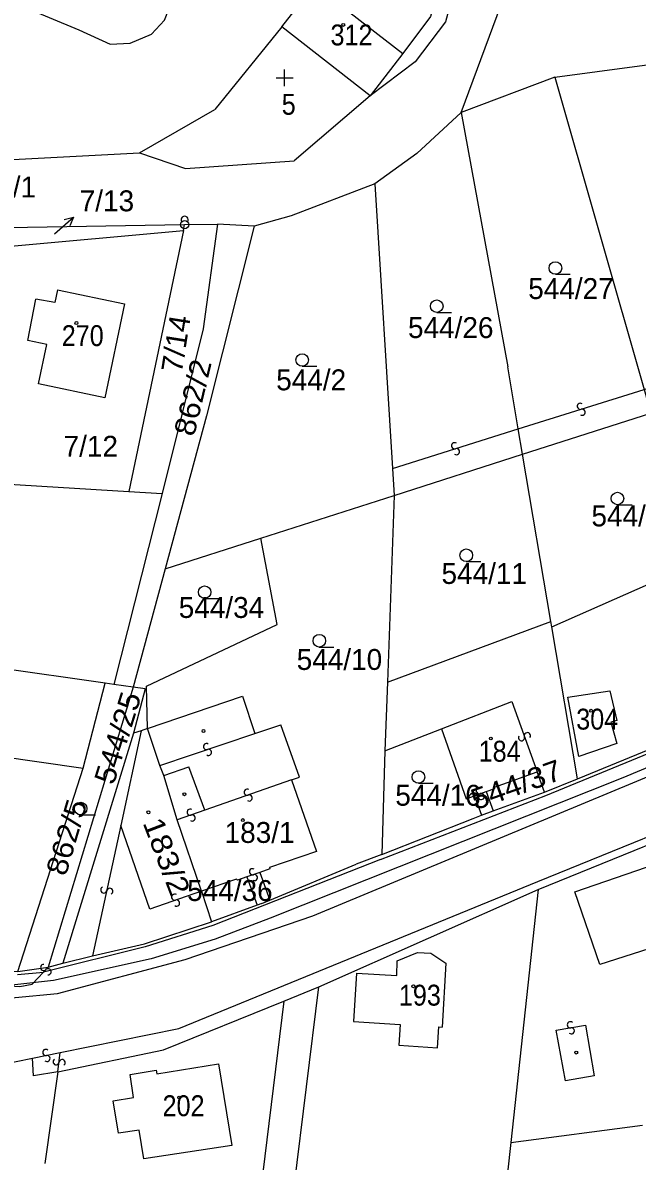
# Model space of a CAD drawing. Extents: x -680102 to -677253, y -1007548 to -1006096.
# Drawn here: x -679602.9 to -679529.5, y -1007099.8 to -1006963.5 of the extents above; entities that cross this region are included whole.
import ezdxf
from ezdxf.enums import TextEntityAlignment as Align

# ---------------------------------------------------------------- set-up
doc = ezdxf.new("R2010")
doc.units = 0
for name, color, linetype, lineweight in [('1', 7, 'Continuous', 25), ('16', 7, 'Continuous', 25), ('24', 7, 'Continuous', 25), ('25', 7, 'Continuous', 25), ('4', 7, 'Continuous', 25)]:
    doc.layers.add(name, color=color, linetype=linetype, lineweight=lineweight)
doc.layers.add('18', color=7, linetype='Continuous')
doc.layers.add('19', color=7, linetype='Continuous')

msp = doc.modelspace()

# ---------------------------------------------------------------- linework, layer by layer
at = {"layer": '1'}
for p, q in [((-679571.97, -1006964), (-679579.98, -1006973.93)), ((-679539.3, -1006970.04), (-679550.54, -1006974.28)), ((-679561.42, -1006972.28), (-679570.49, -1006980.07)), ((-679550.54, -1006974.28), (-679555.81, -1006979.17)), ((-679550.54, -1006974.28), (-679544.95, -1007004.69)), ((-679555.81, -1006979.17), (-679560.85, -1006982.8)), ((-679560.85, -1006982.8), (-679570.85, -1006986.65)), ((-679583.74, -1006988.4), (-679583.59, -1006987.69)), ((-679575.29, -1006987.86), (-679580.97, -1007010.57)), ((-679543.18, -1007015.16), (-679527.83, -1007010.23)), ((-679558.52, -1007020.08), (-679543.18, -1007015.16)), ((-679539.8, -1007035.17), (-679543.18, -1007015.16)), ((-679586.29, -1007019.86), (-679592.07, -1007042.7)), ((-679572.52, -1007035.52), (-679574.48, -1007025.2)), ((-679539.69, -1007035.83), (-679525.44, -1007029.5)), ((-679559.35, -1007042.42), (-679539.8, -1007035.17)), ((-679593.1, -1007042.56), (-679633.83, -1007036.77)), ((-679589.73, -1007043.03), (-679599.91, -1007076.52)), ((-679595.71, -1007052.73), (-679593.1, -1007042.56)), ((-679592.07, -1007042.7), (-679593.1, -1007042.56)), ((-679589.73, -1007043.03), (-679592.07, -1007042.7)), ((-679588.33, -1007043.22), (-679589.73, -1007043.03)), ((-679588.33, -1007043.22), (-679589.71, -1007048.54)), ((-679575.18, -1007048.57), (-679572.07, -1007047.53)), ((-679569.87, -1007053.81), (-679572.07, -1007047.53)), ((-679589.71, -1007048.54), (-679598.16, -1007076.05)), ((-679559.65, -1007050.64), (-679552.89, -1007048.02)), ((-679536.61, -1007054.02), (-679522.23, -1007048.1)), ((-679611.26, -1007050.51), (-679595.71, -1007052.73)), ((-679559.65, -1007050.64), (-679560.02, -1007063.06)), ((-679603.56, -1007077.07), (-679595.71, -1007052.73)), ((-679540.55, -1007055.61), (-679541.44, -1007053.16)), ((-679570.81, -1007054.14), (-679569.87, -1007053.81)), ((-679540.55, -1007055.61), (-679536.61, -1007054.02)), ((-679547.52, -1007055.51), (-679546.68, -1007057.84)), ((-679548.94, -1007056.02), (-679548.09, -1007058.36)), ((-679560.02, -1007063.06), (-679549.1, -1007058.73)), ((-679560.02, -1007063.06), (-679563.08, -1007064.23)), ((-679573.39, -1007064.78), (-679574.59, -1007065.2)), ((-679574.59, -1007065.2), (-679573.42, -1007068.54)), ((-679576.15, -1007065.74), (-679577.28, -1007066.14)), ((-679576.15, -1007065.74), (-679574.91, -1007069.13)), ((-679581.59, -1007067.45), (-679580.36, -1007071.1)), ((-679588.39, -1007073.73), (-679580.36, -1007071.1)), ((-679558.16, -1007075.78), (-679555.74, -1007074.77)), ((-679555.74, -1007074.77), (-679554.15, -1007074.88)), ((-679554.15, -1007074.88), (-679552.34, -1007076.06)), ((-679552.34, -1007076.06), (-679552.81, -1007083.71)), ((-679563.02, -1007077.25), (-679563.39, -1007083.03)), ((-679573.64, -1007128.49), (-679567.53, -1007078.91)), ((-679571.74, -1007080.61), (-679567.53, -1007078.91)), ((-679553.21, -1007083.68), (-679552.81, -1007083.71)), ((-679605.74, -1007088.23), (-679601.79, -1007087.43)), ((-679598.74, -1007089.06), (-679600.32, -1007100.05))]:
    msp.add_line(p, q, dxfattribs=at)
for points in [[(-679550.54, -1006974.28), (-679543.33, -1006954.87), (-679540.17, -1006921.93)], [(-679546.93, -1006924.38), (-679548.35, -1006946.19), (-679548.91, -1006950.64), (-679552.39, -1006963.42), (-679556.03, -1006968.19), (-679561.42, -1006972.28)], [(-679549.48, -1006924.04), (-679550.13, -1006946.36), (-679550.94, -1006951.13), (-679554.18, -1006962.79), (-679557.51, -1006967.2)], [(-679606.93, -1006959.92), (-679596.24, -1006964.38), (-679592.49, -1006966.08), (-679590.1, -1006965.97), (-679587.56, -1006964.91), (-679586.02, -1006963.21), (-679584.89, -1006960.34), (-679584.65, -1006958.11), (-679585.98, -1006955.77), (-679584.33, -1006951.79)], [(-679539.3, -1006970.04), (-679523.55, -1006967.91), (-679513.94, -1007002.8)], [(-679539.3, -1006970.04), (-679528.63, -1007007.41), (-679527.83, -1007010.23)], [(-679610.24, -1006980.22), (-679588.99, -1006979.09), (-679579.98, -1006973.93)], [(-679588.99, -1006979.09), (-679583.5, -1006980.97), (-679570.49, -1006980.07)], [(-679560.85, -1006982.8), (-679558.72, -1007016.85), (-679558.52, -1007020.08)], [(-679609.23, -1006988.1), (-679604.73, -1006988.03), (-679583.59, -1006987.69), (-679579.65, -1006987.63)], [(-679579.65, -1006987.63), (-679581.36, -1007000.14), (-679586.29, -1007019.86)], [(-679570.85, -1006986.65), (-679575.29, -1006987.86), (-679579.65, -1006987.63)], [(-679605.27, -1006990.34), (-679583.74, -1006988.4), (-679590.25, -1007019.62), (-679586.29, -1007019.86)], [(-679605.27, -1006990.34), (-679611.75, -1007018.31), (-679590.25, -1007019.62)], [(-679598.78, -1006995.48), (-679590.77, -1006997.15), (-679593.14, -1007008.42), (-679601.08, -1007006.75), (-679600.09, -1007002.02), (-679602.34, -1007001.54), (-679601.4, -1006996.59)], [(-679598.78, -1006995.48), (-679599.11, -1006997.02), (-679601.4, -1006996.59)], [(-679543.18, -1007015.16), (-679543.69, -1007012.14), (-679544.95, -1007004.69)], [(-679580.97, -1007010.57), (-679585.91, -1007028.87), (-679589.73, -1007043.03)], [(-679585.91, -1007028.87), (-679574.48, -1007025.2), (-679558.52, -1007020.08)], [(-679558.52, -1007020.08), (-679559.35, -1007042.42), (-679559.65, -1007050.64)], [(-679536.61, -1007054.02), (-679539.69, -1007035.83), (-679539.8, -1007035.17)], [(-679588.05, -1007047.98), (-679588.15, -1007042.91), (-679572.52, -1007035.52)], [(-679581.59, -1007067.45), (-679584.47, -1007058.91), (-679586.1, -1007053.62), (-679586.54, -1007052.41), (-679588.05, -1007047.98), (-679576.69, -1007044.12), (-679575.18, -1007048.57)], [(-679514.77, -1007046.84), (-679521.17, -1007049.71), (-679531.18, -1007053.87), (-679573.37, -1007070.68), (-679579.96, -1007073.17), (-679587.61, -1007075.54), (-679599.28, -1007078.15)], [(-679588.05, -1007047.98), (-679588.81, -1007048.24), (-679589.71, -1007048.54)], [(-679552.89, -1007048.02), (-679549.93, -1007056.38), (-679548.94, -1007056.02)], [(-679547.52, -1007055.51), (-679546.49, -1007055.14), (-679546.54, -1007055), (-679541.44, -1007053.16)], [(-679570.81, -1007054.14), (-679567.84, -1007062.68), (-679573.45, -1007064.62), (-679573.39, -1007064.78)], [(-679549.1, -1007058.73), (-679548.09, -1007058.36), (-679546.68, -1007057.84), (-679540.55, -1007055.61)], [(-679567.53, -1007078.91), (-679541.32, -1007067.26), (-679516, -1007056.97)], [(-679574.37, -1007068.93), (-679573.42, -1007068.54), (-679563.08, -1007064.23)], [(-679577.28, -1007066.14), (-679577.37, -1007066), (-679581.59, -1007067.45)], [(-679541.32, -1007067.26), (-679544.6, -1007097.51), (-679528.85, -1007095.43)], [(-679574.37, -1007068.93), (-679574.91, -1007069.13), (-679580.36, -1007071.1)], [(-679599.28, -1007078.15), (-679604.24, -1007078.68), (-679609.24, -1007078.8), (-679614.25, -1007078.59), (-679645.06, -1007075.26), (-679644.83, -1007073.22)], [(-679644.83, -1007073.22), (-679638.88, -1007073.91), (-679622.01, -1007075.9), (-679613.12, -1007076.97), (-679603.56, -1007077.07), (-679599.91, -1007076.52), (-679598.16, -1007076.05)], [(-679598.16, -1007076.05), (-679594.6, -1007075.19), (-679588.39, -1007073.73)], [(-679563.02, -1007077.25), (-679558.23, -1007077.55), (-679558.16, -1007075.78)], [(-679598.74, -1007089.06), (-679586.13, -1007086.43), (-679571.74, -1007080.61), (-679580.62, -1007153.16)], [(-679563.39, -1007083.03), (-679557.8, -1007083.39), (-679557.96, -1007085.88), (-679553.37, -1007086.18), (-679553.21, -1007083.68)], [(-679598.74, -1007089.06), (-679601.65, -1007089.56), (-679601.79, -1007087.43)], [(-679544.6, -1007097.51), (-679547.29, -1007122.2), (-679532.37, -1007118.94)]]:
    msp.add_lwpolyline(points, dxfattribs=at)
for points in [[(-679571.97, -1006964), (-679568.06, -1006959.01), (-679557.51, -1006967.2), (-679561.42, -1006972.28)], [(-679537.78, -1007044.25), (-679532.75, -1007043.46), (-679531.89, -1007047.01), (-679532.62, -1007047.21), (-679531.9, -1007049.79), (-679536.46, -1007051.34)], [(-679579.54, -1007088.11), (-679577.96, -1007097.86), (-679588.49, -1007099.47), (-679589.03, -1007096.03), (-679591.52, -1007096.42), (-679592.13, -1007092.53), (-679589.72, -1007092.15), (-679590.11, -1007089.4), (-679586.99, -1007088.88), (-679586.92, -1007089.3)]]:
    msp.add_lwpolyline(points, close=True, dxfattribs=at)
at = {"layer": '16'}
msp.add_line((-679599.15, -1006988.77), (-679596.9, -1006986.787), dxfattribs=at)
msp.add_lwpolyline([(-679597.981, -1006987.073), (-679596.9, -1006986.787), (-679597.32, -1006987.823)], dxfattribs=at)
at = {"layer": '24'}
for radius in [0.5, 0.022]:
    msp.add_circle((-679583.59, -1006987.69), radius, dxfattribs=at)
msp.add_arc((-679583.591, -1006987.127), 0.437, 328.35109, 209.97456, dxfattribs=at)
at = {"layer": '25'}
for p, q in [((-679571.63, -1006971.11), (-679571.63, -1006969.11)), ((-679572.63, -1006970.11), (-679570.63, -1006970.11)), ((-679539.25, -1006993.63), (-679537.5, -1006993.63)), ((-679553.44, -1006998.2), (-679551.69, -1006998.2)), ((-679569.54, -1007004.63), (-679567.79, -1007004.63)), ((-679531.83, -1007021.21), (-679530.08, -1007021.21)), ((-679549.91, -1007028), (-679548.16, -1007028)), ((-679581.2, -1007032.41), (-679579.45, -1007032.41)), ((-679567.49, -1007038.23), (-679565.74, -1007038.23)), ((-679555.63, -1007054.54), (-679553.88, -1007054.54)), ((-679596.02, -1007058.31), (-679594.27, -1007058.31))]:
    msp.add_line(p, q, dxfattribs=at)
for centre, radius in [((-679564.62, -1006963.79), 0.175), ((-679539.25, -1006992.88), 0.75), ((-679553.44, -1006997.45), 0.75), ((-679596.53, -1006999.46), 0.175), ((-679569.54, -1007003.88), 0.75), ((-679531.83, -1007020.46), 0.75), ((-679549.91, -1007027.25), 0.75), ((-679581.2, -1007031.66), 0.75), ((-679567.49, -1007037.48), 0.75), ((-679534.98, -1007045.85), 0.175), ((-679581.34, -1007048.28), 0.175), ((-679546.97, -1007049.18), 0.175), ((-679555.63, -1007053.79), 0.75), ((-679583.62, -1007055.85), 0.175), ((-679596.02, -1007057.56), 0.75), ((-679587.92, -1007058.01), 0.175), ((-679576.63, -1007058.94), 0.175), ((-679556.24, -1007078.82), 0.175), ((-679536.76, -1007086.76), 0.175), ((-679584.24, -1007092.13), 0.175)]:
    msp.add_circle(centre, radius, dxfattribs=at)
for centre, radius, start, end in [((-679536.267, -1007009.429), 0.367, 54.8081, 286.95578), ((-679536.054, -1007010.133), 0.369, 234.71707, 106.99327), ((-679551.306, -1007014.148), 0.367, 54.59176, 286.76124), ((-679551.095, -1007014.853), 0.369, 234.71707, 106.84448), ((-679543.298, -1007049.081), 0.368, 147.30333, 19.14302), ((-679542.604, -1007048.838), 0.367, 326.81802, 199.42429), ((-679580.975, -1007050.141), 0.368, 56.24518, 288.24001), ((-679580.746, -1007050.84), 0.368, 236.05333, 108.32142), ((-679576.107, -1007055.601), 0.368, 56.61194, 288.29459), ((-679548.352, -1007055.423), 0.367, 56.9842, 289.37321), ((-679548.11, -1007056.118), 0.368, 237.30404, 109.30706), ((-679575.872, -1007056.298), 0.367, 236.14265, 108.73166), ((-679582.937, -1007057.991), 0.368, 56.61194, 288.29459), ((-679582.702, -1007058.688), 0.367, 236.14265, 108.73166), ((-679575.487, -1007065.12), 0.369, 56.39661, 288.20931), ((-679575.252, -1007065.818), 0.367, 236.39491, 108.73166), ((-679593.269, -1007067.307), 0.368, 115.03659, 346.59105), ((-679592.551, -1007067.471), 0.368, 294.69714, 167.28677), ((-679584.787, -1007068.17), 0.369, 56.39661, 288.20931), ((-679584.552, -1007068.868), 0.367, 236.39491, 108.73166), ((-679600.456, -1007076.575), 0.369, 84.3983, 316.21204), ((-679599.923, -1007077.083), 0.368, 263.89131, 136.54329), ((-679537.471, -1007083.428), 0.367, 47.13757, 279.56718), ((-679537.351, -1007084.154), 0.368, 227.42442, 99.39845), ((-679600.199, -1007086.739), 0.367, 48.85898, 280.82299), ((-679600.062, -1007087.462), 0.369, 228.74276, 100.91191), ((-679598.964, -1007087.862), 0.367, 120.54675, 352.49066), ((-679598.235, -1007087.96), 0.369, 300.32599, 172.5914)]:
    msp.add_arc(centre, radius, start, end, dxfattribs=at)
at = {"layer": '4'}
for p, q in [((-679552.89, -1007048.02), (-679544.47, -1007044.76)), ((-679544.47, -1007044.76), (-679541.44, -1007053.16)), ((-679588.81, -1007048.24), (-679591.22, -1007059.58)), ((-679586.54, -1007052.41), (-679575.18, -1007048.57)), ((-679586.1, -1007053.62), (-679583.11, -1007052.58)), ((-679581.17, -1007057.76), (-679583.11, -1007052.58)), ((-679570.81, -1007054.14), (-679581.17, -1007057.76)), ((-679548.94, -1007056.02), (-679547.52, -1007055.51)), ((-679581.17, -1007057.76), (-679584.47, -1007058.91)), ((-679591.22, -1007059.58), (-679594.6, -1007075.19)), ((-679574.59, -1007065.2), (-679576.15, -1007065.74)), ((-679588.3, -1007074.1), (-679600.48, -1007077.13)), ((-679598.8, -1007079.68), (-679583.52, -1007075.61)), ((-679603.57, -1007077.43), (-679600.48, -1007077.13)), ((-679601.83, -1007078.57), (-679600.48, -1007077.13)), ((-679599.91, -1007076.52), (-679600.48, -1007077.13)), ((-679598.74, -1007089.06), (-679598.46, -1007086.76))]:
    msp.add_line(p, q, dxfattribs=at)
for points in [[(-679583.52, -1007075.61), (-679568.28, -1007070.4), (-679510.15, -1007046.23), (-679492.51, -1007036.77), (-679474.86, -1007019.28), (-679449.4, -1006974.77), (-679431.68, -1006958.02), (-679426.67, -1006954.59), (-679411.66, -1006948.44), (-679396.57, -1006943.87), (-679372.18, -1006940.28), (-679288.86, -1006922.55), (-679271.84, -1006918.25), (-679261.74, -1006914.21)], [(-679558.72, -1007016.85), (-679543.69, -1007012.14), (-679528.63, -1007007.41), (-679513.94, -1007002.8)], [(-679560.17, -1007063.64), (-679540.39, -1007056), (-679522.06, -1007048.46)], [(-679584.28, -1007083.89), (-679541.36, -1007066.28), (-679516.03, -1007055.98)], [(-679581.59, -1007067.45), (-679587.75, -1007069.59), (-679591.22, -1007059.58)], [(-679518.1, -1007071.15), (-679533.94, -1007076.21), (-679536.91, -1007067.53), (-679518.51, -1007061.19), (-679516.08, -1007070.02)], [(-679560.17, -1007063.64), (-679580.21, -1007071.56), (-679588.3, -1007074.1)], [(-679638.92, -1007076.45), (-679603.3, -1007078.87), (-679601.83, -1007078.57)], [(-679613.29, -1007081.02), (-679603.88, -1007080.15), (-679598.8, -1007079.68)], [(-679601.79, -1007087.43), (-679598.46, -1007086.76), (-679584.28, -1007083.89)]]:
    msp.add_lwpolyline(points, dxfattribs=at)
msp.add_lwpolyline([(-679539.14, -1007084.09), (-679535.67, -1007083.48), (-679534.6, -1007089.53), (-679538.03, -1007090.14)], close=True, dxfattribs=at)

# ---------------------------------------------------------------- texts
at = {"layer": '16'}
msp.add_text('7/13', height=2.5, dxfattribs=at).set_placement((-679596.14, -1006986.09))
at = {"layer": '18', "width": 0.9}
msp.add_text('5', height=2.5, dxfattribs=at).set_placement((-679571.98, -1006974.54))
at = {"layer": '18'}
for s, height, p in [('867/1', 2.5, (-679609.73, -1006984.44)), ('7/13', 0.1, (-679598.95, -1006988.57)), ('544/27', 2.5, (-679542.5, -1006996.59)), ('544/26', 2.5, (-679556.88, -1007001.26)), ('544/2', 2.5, (-679572.64, -1007007.51)), ('7/12', 2.5, (-679598.07, -1007015.46)), ('544/12', 2.5, (-679534.94, -1007023.79)), ('544/11', 2.5, (-679552.87, -1007030.68)), ('544/34', 2.5, (-679584.3, -1007034.75)), ('544/10', 2.5, (-679570.19, -1007040.97)), ('544/16', 2.5, (-679558.4, -1007057.22))]:
    msp.add_text(s, height=height, dxfattribs=at).set_placement(p)
for s, rotation, width, p in [('7/14', 81.001, 1.05, (-679583.404, -1007002.135)), ('544/37', 19.7, 1.1, (-679543.506, -1007055.882))]:
    msp.add_text(s, height=2.5, rotation=rotation, dxfattribs=dict(at, width=width)).set_placement(p, align=Align.CENTER)
at = {"layer": '18', "width": 1.1}
for s, rotation, p in [('862/2', 76.601, (-679582.468, -1007013.14)), ('544/25', 72.701, (-679592.081, -1007054.84)), ('862/5', 73.501, (-679597.814, -1007065.752))]:
    msp.add_text(s, height=2.5, rotation=rotation, dxfattribs=at).set_placement(p)
at = {"layer": '18'}
msp.add_text('544/36', height=2.5, dxfattribs=at).set_placement((-679578.179, -1007068.62), align=Align.CENTER)
at = {"layer": '19', "width": 0.9}
for s, p in [('312', (-679566.15, -1006966.24)), ('270', (-679598.29, -1007002.22)), ('304', (-679536.76, -1007048.11)), ('184', (-679548.43, -1007051.95)), ('193', (-679557.97, -1007081.14)), ('202', (-679586.23, -1007094.37))]:
    msp.add_text(s, height=2.5, dxfattribs=at).set_placement(p)
at = {"layer": '19', "width": 1.15}
msp.add_text('183/2', height=2.5, rotation=291.002, dxfattribs=at).set_placement((-679586.914, -1007063.742), align=Align.CENTER)
at = {"layer": '19'}
msp.add_text('183/1', height=2.5, dxfattribs=at).set_placement((-679578.81, -1007061.67))

doc.saveas('drawing.dxf')
